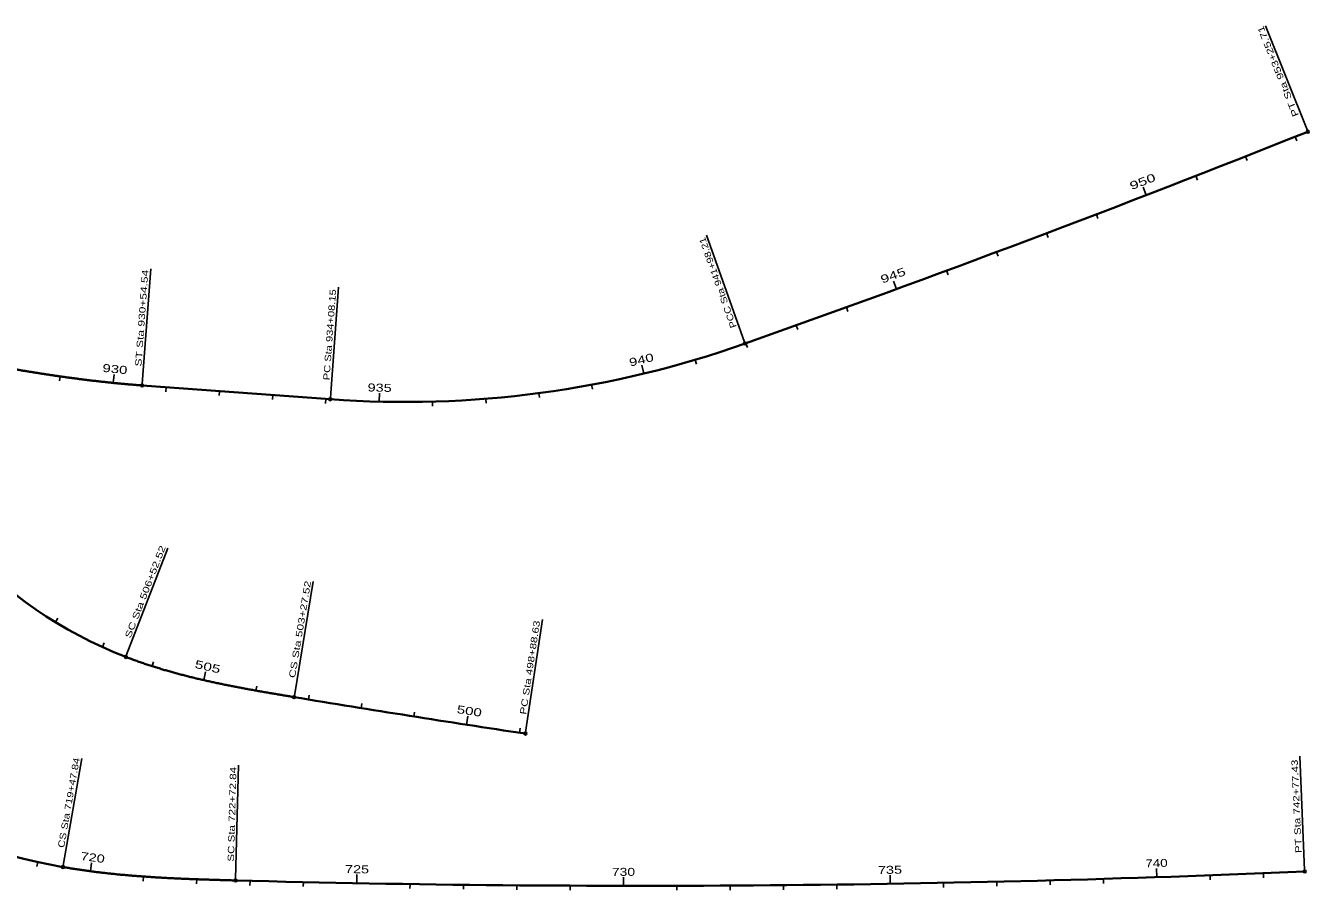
# Model space of a CAD drawing. Extents: x 771045 to 775849, y 632284 to 641017.
# Drawn here: x 773443 to 775849, y 635852 to 637473 of the extents above; entities that cross this region are included whole.
import ezdxf
from ezdxf.enums import TextEntityAlignment as Align

# ---------------------------------------------------------------- set-up
doc = ezdxf.new("R2010")
doc.units = 0
doc.header["$LTSCALE"] = 4.8
for name, color, linetype, lineweight in [('1', 7, 'Continuous', 35), ('30', 7, 'Continuous', 25), ('33', 7, 'Continuous', 25)]:
    doc.layers.add(name, color=color, linetype=linetype, lineweight=lineweight)

msp = doc.modelspace()

# ---------------------------------------------------------------- linework, layer by layer
at = {"layer": '1'}
msp.add_line((773661.118, 636798.54), (774013.778, 636772.631), dxfattribs=at)
for centre, radius, start, end in [((765228.501, 663881.776), 28647.89, 289.49972, 291.75472), ((773711.036, 637024.275), 1145.916, 182.63444, 260.02666), ((774153.717, 638677.356), 1909.859, 265.79806, 289.49972), ((773925.423, 637053.092), 818.511, 195.66665, 248.87721), ((778636.178, 664475.58), 28647.89, 260.57721, 261.45498), ((774597.865, 664508.261), 28647.89, 268.47666, 272.48583)]:
    msp.add_arc(centre, radius, start, end, dxfattribs=at)
for points in [[(773167.929, 636878.44), (773174.545, 636877.07), (773181.162, 636875.7), (773187.778, 636874.33), (773194.395, 636872.962), (773201.012, 636871.595), (773207.629, 636870.229), (773214.247, 636868.865), (773220.865, 636867.504), (773227.484, 636866.145), (773234.103, 636864.789), (773240.723, 636863.436), (773247.344, 636862.086), (773253.965, 636860.74), (773260.587, 636859.399), (773267.21, 636858.062), (773273.835, 636856.729), (773280.46, 636855.402), (773287.086, 636854.08), (773293.713, 636852.764), (773300.342, 636851.454), (773306.971, 636850.15), (773313.602, 636848.853), (773320.235, 636847.562), (773326.869, 636846.279), (773333.504, 636845.004), (773340.141, 636843.737), (773346.779, 636842.478), (773353.419, 636841.227), (773360.061, 636839.985), (773366.704, 636838.753), (773373.35, 636837.53), (773379.996, 636836.317), (773386.645, 636835.114), (773393.296, 636833.922), (773399.949, 636832.74), (773406.603, 636831.569), (773413.26, 636830.41), (773419.918, 636829.263), (773426.579, 636828.128), (773433.242, 636827.005), (773439.907, 636825.895), (773446.574, 636824.798), (773453.243, 636823.715), (773459.915, 636822.645), (773466.589, 636821.589), (773473.265, 636820.548), (773479.943, 636819.521), (773486.624, 636818.509), (773493.306, 636817.513), (773499.992, 636816.532), (773506.679, 636815.568), (773513.369, 636814.619), (773520.061, 636813.687), (773526.756, 636812.772), (773533.453, 636811.875), (773540.152, 636810.995), (773546.853, 636810.133), (773553.557, 636809.289), (773560.263, 636808.464), (773566.972, 636807.658), (773573.683, 636806.871), (773580.396, 636806.103), (773587.111, 636805.356), (773593.828, 636804.628), (773600.548, 636803.922), (773607.27, 636803.236), (773613.994, 636802.571), (773620.72, 636801.928), (773627.448, 636801.307), (773634.178, 636800.708), (773640.91, 636800.131), (773647.645, 636799.578), (773654.38, 636799.047), (773661.118, 636798.54)], [(773945.99, 636214.233), (773941.657, 636214.952), (773937.325, 636215.673), (773932.992, 636216.394), (773928.66, 636217.117), (773924.329, 636217.843), (773919.998, 636218.57), (773915.667, 636219.3), (773911.336, 636220.032), (773907.007, 636220.768), (773902.677, 636221.507), (773898.349, 636222.25), (773894.021, 636222.997), (773889.694, 636223.748), (773885.367, 636224.504), (773881.042, 636225.265), (773876.717, 636226.03), (773872.394, 636226.802), (773868.071, 636227.579), (773863.75, 636228.363), (773859.429, 636229.153), (773855.11, 636229.949), (773850.793, 636230.753), (773846.476, 636231.564), (773842.161, 636232.383), (773837.848, 636233.21), (773833.536, 636234.044), (773829.226, 636234.888), (773824.918, 636235.74), (773820.611, 636236.602), (773816.306, 636237.473), (773812.004, 636238.353), (773807.703, 636239.244), (773803.405, 636240.145), (773799.108, 636241.057), (773794.815, 636241.98), (773790.523, 636242.914), (773786.234, 636243.859), (773781.948, 636244.817), (773777.664, 636245.786), (773773.384, 636246.768), (773769.106, 636247.762), (773764.831, 636248.77), (773760.56, 636249.791), (773756.291, 636250.825), (773752.026, 636251.874), (773747.765, 636252.936), (773743.507, 636254.013), (773739.253, 636255.105), (773735.003, 636256.212), (773730.757, 636257.334), (773726.515, 636258.471), (773722.277, 636259.625), (773718.044, 636260.794), (773713.815, 636261.981), (773709.591, 636263.184), (773705.372, 636264.403), (773701.158, 636265.64), (773696.949, 636266.895), (773692.746, 636268.168), (773688.548, 636269.458), (773684.355, 636270.767), (773680.169, 636272.095), (773675.989, 636273.441), (773671.814, 636274.807), (773667.647, 636276.192), (773663.486, 636277.597), (773659.331, 636279.022), (773655.184, 636280.467), (773651.044, 636281.933), (773646.911, 636283.419), (773642.786, 636284.926), (773638.669, 636286.455), (773634.559, 636288.005), (773630.458, 636289.577)], [(773836.286, 635870.495), (773831.895, 635870.613), (773827.505, 635870.731), (773823.115, 635870.85), (773818.725, 635870.97), (773814.334, 635871.092), (773809.944, 635871.216), (773805.554, 635871.342), (773801.164, 635871.47), (773796.774, 635871.6), (773792.384, 635871.733), (773787.995, 635871.869), (773783.605, 635872.008), (773779.215, 635872.15), (773774.826, 635872.296), (773770.436, 635872.445), (773766.047, 635872.599), (773761.658, 635872.756), (773757.269, 635872.918), (773752.881, 635873.085), (773748.492, 635873.256), (773744.104, 635873.433), (773739.716, 635873.614), (773735.328, 635873.801), (773730.94, 635873.994), (773726.552, 635874.193), (773722.165, 635874.398), (773717.779, 635874.609), (773713.392, 635874.827), (773709.006, 635875.051), (773704.62, 635875.283), (773700.235, 635875.522), (773695.85, 635875.768), (773691.465, 635876.022), (773687.081, 635876.284), (773682.698, 635876.553), (773678.315, 635876.831), (773673.932, 635877.118), (773669.55, 635877.413), (773665.169, 635877.718), (773660.788, 635878.031), (773656.408, 635878.354), (773652.029, 635878.686), (773647.65, 635879.029), (773643.272, 635879.381), (773638.896, 635879.743), (773634.52, 635880.117), (773630.144, 635880.5), (773625.77, 635880.895), (773621.397, 635881.3), (773617.025, 635881.717), (773612.654, 635882.146), (773608.284, 635882.586), (773603.916, 635883.039), (773599.549, 635883.503), (773595.183, 635883.98), (773590.818, 635884.469), (773586.455, 635884.971), (773582.094, 635885.487), (773577.734, 635886.015), (773573.375, 635886.557), (773569.019, 635887.113), (773564.664, 635887.682), (773560.311, 635888.266), (773555.96, 635888.864), (773551.611, 635889.476), (773547.264, 635890.104), (773542.919, 635890.746), (773538.577, 635891.403), (773534.237, 635892.076), (773529.899, 635892.764), (773525.564, 635893.468), (773521.231, 635894.187), (773516.902, 635894.923), (773512.575, 635895.676)]]:
    msp.add_spline(points, degree=3, dxfattribs=at)
at = {"layer": '30'}
for p, q in [((775822.504, 637264.701), (775825.647, 637256.804)), ((775729.528, 637227.883), (775732.644, 637219.975)), ((775636.425, 637191.39), (775639.513, 637183.471)), ((775543.195, 637155.222), (775537.434, 637170.149)), ((775449.839, 637119.38), (775452.871, 637111.44)), ((775356.358, 637083.864), (775359.363, 637075.913)), ((775262.754, 637048.675), (775265.731, 637040.713)), ((775075.181, 636979.277), (775069.682, 636994.302)), ((775169.028, 637013.812), (775171.978, 637005.84)), ((774981.214, 636945.069), (774984.107, 636937.077)), ((774887.128, 636911.19), (774889.993, 636903.188)), ((774792.924, 636877.64), (774795.762, 636869.627)), ((774601.3, 636820.684), (774597.551, 636836.238)), ((774697.858, 636846.653), (774700.28, 636838.506)), ((773507.536, 636815.445), (773506.335, 636807.03)), ((773606.787, 636803.284), (773608.389, 636819.204)), ((774503.516, 636799.804), (774505.073, 636791.448)), ((773706.456, 636795.209), (773705.833, 636786.732)), ((773806.187, 636787.882), (773805.564, 636779.405)), ((773905.918, 636780.555), (773905.296, 636772.078)), ((774105.507, 636768.105), (774105.911, 636784.1)), ((774404.773, 636784.07), (774405.891, 636775.644)), ((774005.65, 636773.228), (774005.027, 636764.751)), ((774205.496, 636768.199), (774205.726, 636759.702)), ((774305.342, 636773.525), (774306.017, 636765.052)), ((773498.405, 636354.797), (773502.839, 636362.049)), ((773586.688, 636307.962), (773590.206, 636315.7)), ((773679.994, 636272.151), (773682.583, 636280.247)), ((773776.497, 636246.052), (773780.064, 636261.65)), ((773874.541, 636226.418), (773876.034, 636234.786)), ((773973.139, 636209.74), (773974.523, 636218.127)), ((774071.834, 636193.636), (774073.188, 636202.027)), ((774170.584, 636177.875), (774171.909, 636186.272)), ((774269.389, 636162.46), (774271.828, 636178.273)), ((774368.247, 636147.39), (774369.513, 636155.795)), ((773465.64, 635904.943), (773463.82, 635896.64)), ((773564.121, 635887.754), (773566.228, 635903.615)), ((775563.169, 635876.639), (775562.63, 635892.629)), ((773663.612, 635877.828), (773663.008, 635869.349)), ((773763.475, 635872.691), (773763.169, 635864.196)), ((773863.432, 635869.786), (773863.214, 635861.289)), ((773963.403, 635867.397), (773963.215, 635858.899)), ((774063.383, 635865.357), (774063.681, 635881.354)), ((774163.368, 635863.666), (774163.239, 635855.167)), ((774263.359, 635862.324), (774263.26, 635853.824)), ((774563.352, 635860.392), (774563.371, 635876.392)), ((774863.348, 635861.601), (774863.427, 635853.101)), ((774963.342, 635862.702), (774963.45, 635854.203)), ((775063.331, 635864.152), (775063.071, 635880.15)), ((775163.315, 635865.952), (775163.483, 635857.453)), ((775263.292, 635868.1), (775263.489, 635859.602)), ((775363.261, 635870.597), (775363.488, 635862.1)), ((775463.22, 635873.443), (775463.477, 635864.947)), ((775663.106, 635880.182), (775663.422, 635871.688)), ((775763.03, 635884.075), (775763.376, 635875.582)), ((774363.354, 635861.331), (774363.285, 635852.831)), ((774463.352, 635860.686), (774463.312, 635852.187)), ((774663.352, 635860.446), (774663.371, 635851.946)), ((774763.351, 635860.849), (774763.4, 635852.349))]:
    msp.add_line(p, q, dxfattribs=at)
at = {"layer": '33'}
for p, q in [((775845.382, 637276.725), (775767.14, 637472.793)), ((774790.331, 636879.586), (774719.313, 637080.139)), ((773661.316, 636801.233), (773677.165, 637016.951)), ((774013.976, 636775.323), (774029.218, 636982.796)), ((773631.431, 636292.095), (773709.293, 636493.641)), ((773946.432, 636216.896), (773981.999, 636431.209)), ((774379.891, 636148.368), (774411.644, 636359.696)), ((775840.272, 635890.027), (775830.994, 636103.762)), ((773513.042, 635898.335), (773548.376, 636099.268)), ((773836.358, 635873.195), (773842.026, 636086.348))]:
    msp.add_line(p, q, dxfattribs=at)
for centre in [(775846.383, 637274.218), (774791.232, 636877.041), (773661.118, 636798.54), (774013.778, 636772.631), (773630.458, 636289.577), (773945.99, 636214.233), (774379.49, 636145.698), (773512.575, 635895.676), (775840.389, 635887.329), (773836.286, 635870.496)]:
    msp.add_circle(centre, 2.7, dxfattribs=at)

# ---------------------------------------------------------------- texts
at = {"layer": '30'}
for s, rotation, width, p in [('950', 21.103, 1.5, (775539.162, 637173.71)), ('945', 20.103, 1.45, (775071.331, 636997.781)), ('940', 13.554, 1.4, (774598.676, 636839.287)), ('930', 354.251, 1.4, (773609.411, 636821.815)), ('935', 358.554, 1.35, (774106.169, 636786.795)), ('505', 347.12, 1.45, (773782.337, 636263.9)), ('500', 351.232, 1.4, (774273.382, 636180.765)), ('720', 352.434, 1.35, (773567.571, 635906.16)), ('740', 1.931, 1.25, (775562.791, 635895.336)), ('725', 358.931, 1.35, (774063.871, 635884.051)), ('730', 359.931, 1.3, (774563.383, 635879.092)), ('735', 0.931, 1.35, (775063.149, 635882.852))]:
    msp.add_text(s, height=15, rotation=rotation, dxfattribs=dict(at, width=width)).set_placement(p, align=Align.CENTER)
at = {"layer": '33'}
for s, rotation, width, p in [('PT Sta 953+25.71', 111.755, 1.4, (775829.695, 637305.242)), ('PCC Sta 941+98.21', 109.5, 1.25, (774775.779, 636908.698)), ('ST Sta 930+54.54', 85.798, 1.4, (773659.693, 636833.739)), ('PC Sta 934+08.15', 85.798, 1.3, (774012.353, 636807.83)), ('SC Sta 506+52.52', 68.877, 1.4, (773639.34, 636323.666)), ('CS Sta 503+27.52', 80.577, 1.4, (773947.774, 636249.415)), ('PC Sta 498+88.63', 81.455, 1.35, (774380.735, 636180.904)), ('CS Sta 719+47.84', 80.027, 1.3, (773514.697, 635930.84)), ('SC Sta 722+72.84', 88.477, 1.35, (773833.218, 635905.589)), ('PT Sta 742+77.43', 92.486, 1.35, (775834.875, 635922.122))]:
    msp.add_text(s, height=12, rotation=rotation, dxfattribs=dict(at, width=width)).set_placement(p)

doc.saveas('drawing.dxf')
